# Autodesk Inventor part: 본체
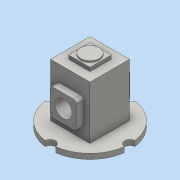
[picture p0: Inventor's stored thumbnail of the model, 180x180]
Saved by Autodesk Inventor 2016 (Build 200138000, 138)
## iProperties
Created: 2018-07
Part Number: 본체
Material: 일반
Document SubType Name: Modeling
Designer: 2-
Density: 1 g/cm^3
Appearance: 기본값
Author: 2-
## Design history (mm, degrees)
sketch "스케치1"
  geometry: C1 r 75 at (0, 0); 1 further point
  constraints: 1 centre point, 1 coincident
  dimensions: "d0" = 150 diameter of C1
extrude "돌출1" new body sketch "스케치1" distance "d1" = 10; taper "d2" = 0 deg
sketch "스케치2"
  geometry: L1 (0, 0)-(75, 0); C1 r 10 at (75, 0); 1 further point
  constraints: 2 end point, 1 centre point, 1 coincident, 1 horizontal, 1 horizontal alignment, 1 other
  dimensions: "d3" = 20 diameter of C1
extrude "돌출2" cut sketch "스케치2" distance "d4" = 10; taper "d5" = 0 deg
sketch "스케치3"
  geometry: L1 (-37, -37)-(37, -37); L2 (37, -37)-(37, 37); L3 (37, 37)-(-37, 37); L4 (-37, 37)-(-37, -37); L5 (-37, -37)-(37, 37); L6 (37, -37)-(-37, 37); 1 further point
  constraints: 12 end point, 2 midpoint, 2 parallel, 1 horizontal, 1 perpendicular
  dimensions: "d9" = 74 distance of L3.end L2.end; "d10" = 74 distance of L2.end L1.end
extrude "돌출3" join sketch "스케치3" distance "d11" = 100; taper "d12" = 0 deg
sketch "스케치4"
  geometry: L1 (20, -20)-(-20, -20); L2 (-20, -20)-(-20, 20); L3 (-20, 20)-(20, 20); L4 (20, 20)-(20, -20); L5 (20, -20)-(-20, 20); L6 (-20, -20)-(20, 20); 1 further point
  constraints: 12 end point, 2 midpoint, 2 parallel, 1 horizontal, 1 perpendicular
  dimensions: "d13" = 40 distance of L2.end L3.end; "d14" = 40 distance of L1.end L2.end
extrude "돌출4" join sketch "스케치4" distance "d15" = 7; taper "d16" = 0 deg
sketch "스케치5"
  geometry: C1 r 17.5 at (0, 0); 1 further point
  constraints: 1 centre point, 1 coincident
  dimensions: "d17" = 35 diameter of C1
extrude "돌출5" join sketch "스케치5" distance "d18" = 3; taper "d19" = 0 deg
sketch "스케치6"
  geometry: L1 (32, 32)-(-32, 32); L2 (-32, 32)-(-32, -32); L3 (-32, -32)-(32, -32); L4 (32, -32)-(32, 32); L5 (32, 32)-(-32, -32); L6 (-32, 32)-(32, -32); 1 further point
  constraints: 12 end point, 2 midpoint, 2 parallel, 1 horizontal, 1 perpendicular
  dimensions: "d20" = 64 distance of L3.end L2.end; "d21" = 64 distance of L2.end L1.end
extrude "돌출6" cut sketch "스케치6" distance "d22" = 105; taper "d23" = 0 deg
sketch "스케치7"
  geometry: L1 (37, -10)-(37, 45); L2 (12, 20)-(62, 20); L3 (62, 20)-(62, 70); L4 (62, 70)-(12, 70); L5 (12, 70)-(12, 20); L6 (12, 20)-(62, 70); L7 (62, 20)-(12, 70)
  constraints: 14 end point, 2 midpoint, 2 parallel, 1 horizontal, 1 perpendicular, 1 vertical
  dimensions: "d24" = 55 distance of L1.start L1.end; "d25" = 50 distance of L4.end L3.end; "d26" = 50 distance of L3.end L2.end
extrude "돌출7" join sketch "스케치7" distance "d27" = 13; taper "d28" = 0 deg
sketch "스케치8"
  geometry: L1 (-50, 80)-(-50, 30) reference; L2 (-50, 55)-(50, 55); L3 (50, 80)-(50, 30) reference; L4 (-37, 80)-(-50, 80) reference; L5 (-32, 0)-(-32, 105) reference; L6 (-32, 80)-(-25, 77.452); L7 (-32, 80)-(-24.551, 80); L8 (-25, 77.452)-(-25, 55); L9 (-32, 80)-(-32, 55); 1 further point
  constraints: 10 end point, 4 point on line, 2 midpoint, 1 equal length, 1 horizontal, 1 perpendicular
  dimensions: "d30" = 7 horizontal distance of L6.end L6.start; "d31" = 110 deg angle of L5 L6; "d32" = 50 diameter of L6.start L2
revolve "회전1" sketch "스케치8" stored, may be unused: angle "d33" = 90 deg
sketch "스케치9"
  geometry: C1 r 25 at (37, 45) reference; C2 r 16 at (37, 45); 1 further point
  constraints: 1 centre point, 1 coincident
  dimensions: "d34" = 32 diameter of C2
extrude "돌출8" cut sketch "스케치9" distance "d35" = 100; taper "d36" = 0 deg
fillet "모깎기1" dims "d37" = 6
sketch "스케치10"
  geometry: A1 r 6 centre (18, 64) between (18, 70) and (12, 64) reference; A2 r 6 centre (56, 64) between (62, 64) and (56, 70) reference; A3 r 6 centre (56, 26) between (56, 20) and (62, 26) reference; A4 r 6 centre (18, 26) between (12, 26) and (18, 20) reference; 5 further points
  constraints: 4 coincident
hole "구멍1" sketch "스케치10" at (18, 64), (56, 64), (56, 26), (18, 26) diameter "d38" = 3.242; stored, may be unused: countersink angle "d42" = 90 deg, drill point angle "d44" = 118 deg; dims "d39" = 8, "d40" = 4, "d41" = 2, "d43" = 10
node "솔리드1"
pattern_circular "원형 패턴1" dims angle "d7" = 360 deg
mirror "대칭1"
mirror "대칭2"
